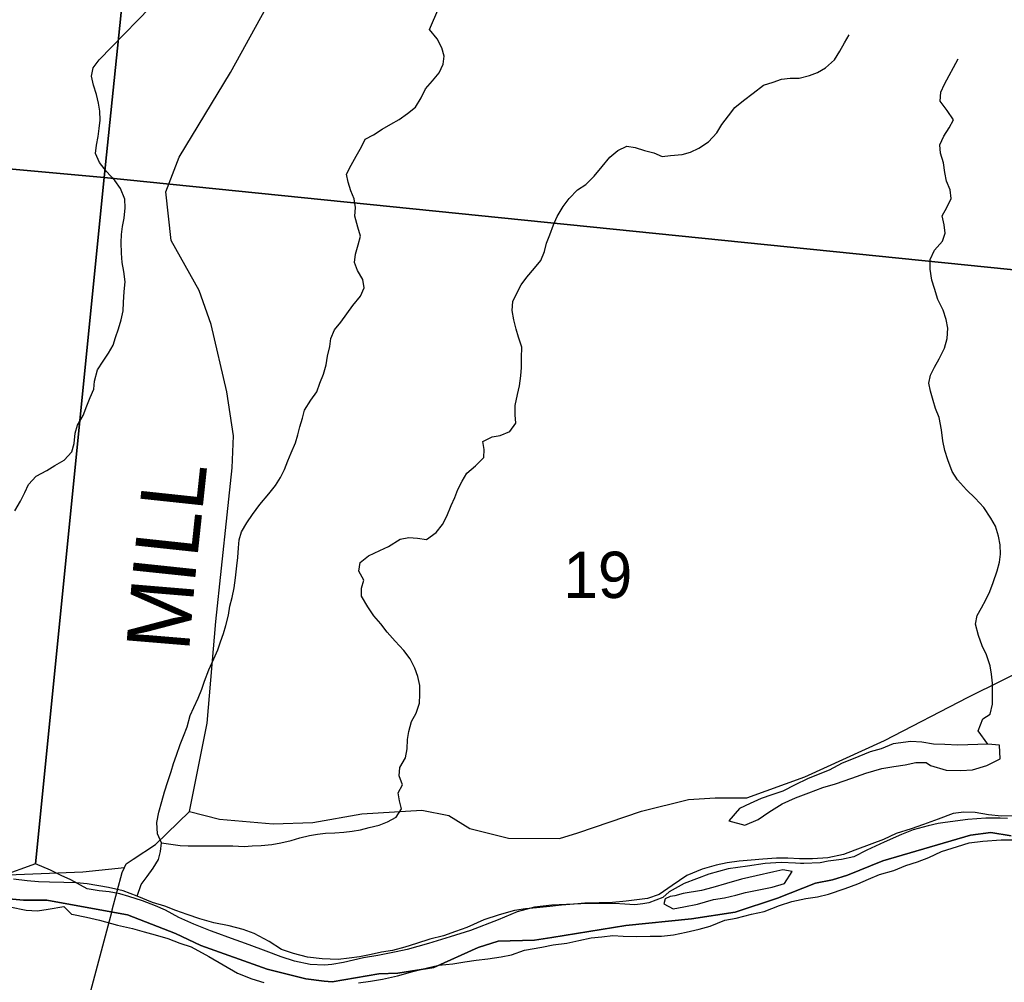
# Model space of a CAD drawing. Extents: x 0 to 34, y -4 to 22.
# Drawn here: x 7.021 to 7.647, y 17.313 to 17.925 of the extents above; entities that cross this region are included whole.
import ezdxf

# ---------------------------------------------------------------- set-up
doc = ezdxf.new("R2010")
doc.units = 0
for name, color, linetype in [('GM_X_County_Road', 7, 'Continuous'), ('GM_X_County_Road_Text', 7, 'Continuous'), ('GM_X_Major_River', 7, 'Continuous'), ('GM_X_Minor_Lake', 7, 'Continuous'), ('GM_X_Minor_River', 7, 'Continuous'), ('GM_X_Section', 7, 'Continuous'), ('GM_X_Section_Text', 7, 'Continuous'), ('GM_X_Township', 7, 'Continuous')]:
    doc.layers.add(name, color=color, linetype=linetype)

msp = doc.modelspace()

# ---------------------------------------------------------------- linework, layer by layer
at = {"layer": 'GM_X_County_Road'}
for points in [[(7.09297, 17.39172), (7.10722, 17.40105), (7.12874, 17.42204), (7.13996, 17.47822), (7.14547, 17.54279), (7.15263, 17.61054), (7.15587, 17.64042), (7.1568, 17.66071), (7.15252, 17.68885), (7.14264, 17.73152), (7.13503, 17.75305), (7.11718, 17.78491), (7.11377, 17.81597), (7.1222, 17.838), (7.15476, 17.89165), (7.19681, 17.96794), (7.24156, 18.04266), (7.28905, 18.14179), (7.32426, 18.22106), (7.33601, 18.25915), (7.33871, 18.2913)], [(7.12874, 17.42204), (7.14789, 17.41714), (7.18205, 17.41411), (7.2072, 17.41498), (7.23831, 17.42056), (7.27658, 17.4228), (7.29363, 17.41955), (7.3071, 17.41129), (7.33158, 17.40496), (7.36392, 17.4049), (7.37576, 17.40842), (7.41611, 17.42211), (7.44593, 17.42959), (7.46306, 17.43061), (7.48311, 17.43078), (7.51998, 17.444), (7.57068, 17.46712), (7.62387, 17.49475), (7.66704, 17.51613), (7.71322, 17.5294), (7.71345, 17.52946)], [(7.07972, 17.35945), (7.08603, 17.38326), (7.08749, 17.38649), (7.08854, 17.38883), (7.09297, 17.39172)], [(6.99189, 17.38097), (7.06091, 17.38372), (7.08749, 17.38649)], [(7.02824, 17.00931), (7.02778, 17.03262), (7.02845, 17.09594), (7.02658, 17.11041), (7.02352, 17.16044), (7.02324, 17.17355), (7.02614, 17.18552), (7.04401, 17.22581), (7.05004, 17.24762), (7.07789, 17.35259), (7.07935, 17.35808), (7.07972, 17.35945)]]:
    msp.add_lwpolyline(points, dxfattribs=at)
at = {"layer": 'GM_X_Major_River'}
for points in [[(7.65438, 17.41915), (7.64501, 17.41912), (7.63673, 17.41986), (7.62821, 17.42141), (7.62099, 17.42159), (7.61427, 17.42069), (7.60482, 17.41719), (7.59536, 17.41368), (7.58752, 17.41094), (7.57808, 17.40797), (7.56995, 17.40416), (7.56265, 17.4014), (7.55184, 17.3974), (7.54455, 17.39464), (7.53459, 17.39248), (7.52494, 17.39192), (7.51664, 17.39186), (7.50916, 17.39232), (7.50193, 17.39223), (7.49335, 17.39164), (7.48584, 17.39103), (7.47833, 17.39042), (7.47054, 17.38927), (7.46354, 17.38784), (7.45464, 17.38539), (7.44491, 17.38136), (7.43564, 17.37491), (7.42746, 17.36923), (7.4199, 17.36675), (7.41319, 17.36585), (7.40647, 17.36495), (7.39762, 17.3641), (7.38932, 17.36404), (7.38021, 17.36374), (7.37324, 17.36311), (7.36519, 17.36251), (7.35794, 17.36162), (7.34936, 17.36076), (7.34238, 17.36014)], [(7.39788, 17.34325), (7.40457, 17.34281), (7.41286, 17.3426), (7.42169, 17.34265), (7.42892, 17.34274), (7.43644, 17.34362), (7.44451, 17.34529), (7.45286, 17.34722), (7.45987, 17.34918), (7.46906, 17.35296), (7.47632, 17.35411), (7.48603, 17.35681), (7.4941, 17.35848), (7.50383, 17.36225), (7.51166, 17.36472), (7.52054, 17.36664), (7.52806, 17.36779), (7.53507, 17.36948), (7.54559, 17.37296), (7.5537, 17.37597), (7.56047, 17.379), (7.56751, 17.38204), (7.57667, 17.38448), (7.58425, 17.38776), (7.59153, 17.38999), (7.59883, 17.39275), (7.60696, 17.39655), (7.61695, 17.39978), (7.6245, 17.40199), (7.63309, 17.40312), (7.64489, 17.40389), (7.65372, 17.40394)], [(7.51189, 17.38396), (7.50602, 17.38491), (7.50037, 17.38372), (7.48906, 17.38106), (7.47964, 17.37889), (7.4702, 17.37618), (7.46157, 17.37373), (7.45429, 17.37177), (7.44273, 17.36992), (7.43734, 17.36845), (7.43439, 17.36799), (7.43114, 17.36647), (7.43025, 17.36328), (7.43633, 17.36019), (7.44305, 17.36136), (7.45166, 17.36302), (7.46191, 17.36597)], [(7.46191, 17.36597), (7.46889, 17.36713), (7.47616, 17.36882), (7.48237, 17.37054), (7.4907, 17.3722), (7.49931, 17.37385), (7.50714, 17.37633), (7.51189, 17.38396)], [(7.34238, 17.36014), (7.33539, 17.35897), (7.32569, 17.35628), (7.31597, 17.35304), (7.30514, 17.34824), (7.29785, 17.34575), (7.29028, 17.343), (7.28166, 17.34081), (7.27303, 17.33808), (7.26574, 17.33586), (7.25792, 17.33365), (7.25093, 17.33249), (7.2442, 17.33105), (7.23694, 17.32963), (7.23023, 17.32873), (7.22324, 17.32783), (7.21309, 17.32835), (7.20375, 17.32939), (7.19497, 17.33175), (7.18728, 17.33434), (7.17938, 17.33935), (7.16987, 17.3444), (7.16298, 17.34698), (7.15394, 17.34934), (7.14435, 17.35119), (7.13532, 17.35382), (7.12736, 17.35642), (7.1202, 17.35901), (7.11305, 17.36186), (7.10534, 17.36419), (7.09554, 17.36818), (7.08653, 17.37161), (7.07722, 17.37371), (7.06363, 17.37592), (7.05695, 17.37662), (7.04893, 17.37682), (7.03983, 17.37705), (7.03288, 17.37722), (7.02567, 17.37794), (7.01686, 17.37896)], [(7.01454, 17.36138), (7.02492, 17.35925), (7.03213, 17.3588), (7.03886, 17.35997), (7.0488, 17.36159), (7.0538, 17.35682)], [(7.0538, 17.35682), (7.05403, 17.35665), (7.06335, 17.35481), (7.0716, 17.353), (7.08302, 17.34978), (7.09261, 17.34767), (7.10005, 17.34561), (7.10695, 17.34357), (7.11492, 17.34123), (7.12261, 17.33836), (7.12978, 17.33605), (7.14113, 17.32988), (7.15009, 17.32458), (7.15932, 17.31927), (7.16833, 17.31557), (7.17603, 17.31324)], [(7.23625, 17.31307), (7.24377, 17.31422), (7.25156, 17.31536), (7.26099, 17.31753), (7.27069, 17.32023), (7.28012, 17.32267), (7.28739, 17.32436), (7.29625, 17.32521), (7.30377, 17.32635), (7.31103, 17.32751), (7.31854, 17.32839), (7.32687, 17.32952), (7.3336, 17.33095), (7.34171, 17.33396), (7.35273, 17.33582), (7.35999, 17.33724), (7.36859, 17.33837), (7.37639, 17.34004), (7.38419, 17.34172), (7.3909, 17.34235), (7.39788, 17.34325)]]:
    msp.add_lwpolyline(points, dxfattribs=at)
at = {"layer": 'GM_X_Minor_Lake'}
for points in [[(7.63629, 17.46478), (7.61727, 17.46419), (7.60898, 17.46466), (7.60176, 17.46484), (7.5943, 17.4661), (7.58735, 17.46654), (7.57607, 17.46495), (7.5685, 17.46193), (7.56149, 17.45997), (7.55067, 17.45543), (7.54363, 17.45266), (7.53549, 17.44832), (7.52846, 17.44556), (7.5217, 17.44279), (7.51384, 17.43898), (7.50597, 17.43489), (7.49896, 17.43266), (7.4922, 17.43016), (7.48516, 17.42713), (7.47839, 17.42382), (7.47176, 17.41597), (7.48186, 17.41331), (7.49025, 17.41684), (7.49706, 17.42149), (7.5055, 17.42689), (7.51416, 17.43068), (7.52254, 17.43395), (7.53146, 17.4372), (7.53955, 17.43967), (7.54981, 17.44315), (7.55873, 17.4464), (7.56898, 17.44936), (7.5765, 17.4505), (7.58376, 17.45166), (7.59049, 17.4531), (7.59718, 17.45319)], [(7.59718, 17.45319), (7.59981, 17.45126), (7.6099, 17.44833), (7.61926, 17.4481), (7.6265, 17.44845), (7.63567, 17.45116), (7.64408, 17.4555), (7.64376, 17.46406), (7.63629, 17.46478)]]:
    msp.add_lwpolyline(points, dxfattribs=at)
at = {"layer": 'GM_X_Minor_River'}
for points in [[(7.0178, 17.61319), (7.02138, 17.61928), (7.02415, 17.62485), (7.02637, 17.62989), (7.03127, 17.63516), (7.03802, 17.6388), (7.04316, 17.64192), (7.0491, 17.6453), (7.054, 17.65057), (7.05543, 17.6559), (7.05608, 17.66257), (7.0575, 17.66763), (7.06108, 17.67372), (7.06359, 17.67983), (7.06555, 17.68514), (7.06805, 17.69045), (7.0684, 17.69552), (7.07039, 17.70271), (7.07396, 17.70826), (7.07726, 17.71329), (7.08028, 17.71832), (7.08171, 17.72338), (7.08367, 17.72869), (7.08537, 17.73455), (7.08654, 17.74014), (7.08689, 17.74548), (7.08728, 17.75243), (7.08792, 17.75857), (7.08696, 17.76527), (7.08598, 17.7709), (7.08555, 17.77678), (7.0854, 17.78374), (7.08548, 17.78881), (7.0861, 17.79388), (7.08726, 17.79921), (7.0879, 17.80562), (7.08773, 17.81123), (7.0849, 17.81796), (7.08124, 17.8231), (7.07599, 17.8288), (7.07154, 17.83448), (7.06896, 17.84014), (7.06958, 17.84547), (7.07075, 17.85107), (7.07137, 17.85614), (7.07199, 17.86147), (7.07182, 17.86709), (7.07083, 17.87218), (7.06959, 17.87782), (7.06782, 17.88373), (7.06658, 17.88936), (7.06747, 17.89469), (7.0713, 17.89971), (7.11193, 17.9415)], [(7.09554, 17.36818), (7.09806, 17.3756), (7.10189, 17.38062), (7.10572, 17.3859), (7.10903, 17.39146), (7.11045, 17.39652), (7.11108, 17.40212), (7.1085, 17.40778), (7.10809, 17.415), (7.10927, 17.42167), (7.11125, 17.42832), (7.11296, 17.43444), (7.11495, 17.44109), (7.11719, 17.44747), (7.11861, 17.45253), (7.12058, 17.45784), (7.12283, 17.46449), (7.12506, 17.4698), (7.1273, 17.47591), (7.12929, 17.4831), (7.13152, 17.48814), (7.13429, 17.49398), (7.13653, 17.49983), (7.13822, 17.50488), (7.14101, 17.51205), (7.14434, 17.51895), (7.14685, 17.52479), (7.14854, 17.52984), (7.1505, 17.53516), (7.15192, 17.54021), (7.15364, 17.54687), (7.15453, 17.55247), (7.15597, 17.55806), (7.15714, 17.56419), (7.15805, 17.57059), (7.15898, 17.57806), (7.1596, 17.5834), (7.15997, 17.58954), (7.16032, 17.59462), (7.16175, 17.59967), (7.16532, 17.6055), (7.16889, 17.61079), (7.17354, 17.61713), (7.17927, 17.62399), (7.18338, 17.62927), (7.18667, 17.63429), (7.18916, 17.63933), (7.19139, 17.64491), (7.19335, 17.64996), (7.19613, 17.65633), (7.19756, 17.66139), (7.19898, 17.66644), (7.20068, 17.67203), (7.20183, 17.67709), (7.20595, 17.68344), (7.20979, 17.68873), (7.21175, 17.69431), (7.21399, 17.69989), (7.21569, 17.70601), (7.21659, 17.71134), (7.21803, 17.71747), (7.21865, 17.72254), (7.22088, 17.72812), (7.22498, 17.73313), (7.22881, 17.73842), (7.23265, 17.7437), (7.23756, 17.7495), (7.23979, 17.75481), (7.23907, 17.76017), (7.23569, 17.76584), (7.23364, 17.77095), (7.23426, 17.77629), (7.23597, 17.78214), (7.2374, 17.78773), (7.23589, 17.79337), (7.23386, 17.80035), (7.23423, 17.80596), (7.23351, 17.81132), (7.23146, 17.81643), (7.22968, 17.82207), (7.2287, 17.82717), (7.23147, 17.83274), (7.23477, 17.83857), (7.23808, 17.84439), (7.24057, 17.84943), (7.2457, 17.85202), (7.25138, 17.85568), (7.25678, 17.8588), (7.26218, 17.86192), (7.26733, 17.86558), (7.27248, 17.86978), (7.27605, 17.8756), (7.27883, 17.88144), (7.28319, 17.88645), (7.28756, 17.89146), (7.29006, 17.89703), (7.29068, 17.9021), (7.28916, 17.90747), (7.28632, 17.91313), (7.28133, 17.91909), (7.29263, 17.94527)], [(7.36252, 17.80017), (7.36638, 17.80653), (7.3702, 17.81155), (7.37538, 17.81708), (7.38079, 17.82047), (7.38596, 17.82573), (7.39115, 17.83206), (7.39606, 17.83787), (7.40121, 17.84206), (7.40688, 17.84491), (7.41221, 17.84403), (7.41806, 17.84206), (7.42392, 17.84063), (7.42924, 17.83841), (7.43459, 17.83886), (7.44209, 17.83954), (7.4472, 17.84106), (7.4526, 17.84365), (7.45881, 17.84756), (7.46399, 17.85336), (7.46729, 17.85865), (7.4714, 17.8642), (7.4755, 17.86948), (7.48092, 17.87394), (7.48715, 17.87865), (7.49366, 17.88363), (7.49985, 17.88567), (7.50522, 17.88745), (7.51059, 17.88817), (7.51647, 17.88808), (7.52292, 17.88984), (7.52803, 17.89163), (7.53317, 17.89476), (7.53887, 17.89975), (7.54217, 17.90531), (7.5452, 17.91061), (7.54823, 17.91564)], [(7.63629, 17.46478), (7.63013, 17.47325), (7.63324, 17.48091), (7.6378, 17.48382), (7.63924, 17.49021), (7.63934, 17.49609), (7.6392, 17.50358), (7.63876, 17.5092), (7.63778, 17.51456), (7.63549, 17.52155), (7.63264, 17.52721), (7.63035, 17.53393), (7.6286, 17.54117), (7.62949, 17.54651), (7.63225, 17.55154), (7.63501, 17.55658), (7.63751, 17.56188), (7.63974, 17.56746), (7.64227, 17.5749), (7.6437, 17.5805), (7.64432, 17.58557), (7.64416, 17.59145), (7.64318, 17.59708), (7.64114, 17.60326), (7.63829, 17.60838), (7.63385, 17.61514), (7.62834, 17.62111), (7.62281, 17.62654), (7.61703, 17.63278), (7.61365, 17.63818), (7.61083, 17.64545), (7.60905, 17.65136), (7.60782, 17.65752), (7.60687, 17.66449), (7.6054, 17.67253), (7.60308, 17.67818), (7.60156, 17.68329), (7.59979, 17.6892), (7.59881, 17.69429), (7.59996, 17.69935), (7.60245, 17.70439), (7.60549, 17.70969), (7.60881, 17.71659), (7.61052, 17.72271), (7.61089, 17.72912), (7.60992, 17.73475), (7.60788, 17.74066), (7.60452, 17.7474), (7.60249, 17.75438), (7.60071, 17.75975), (7.59976, 17.76672), (7.59959, 17.77287), (7.60237, 17.77871), (7.60755, 17.78451), (7.60924, 17.78956), (7.60852, 17.79492), (7.60728, 17.80055), (7.61031, 17.80585), (7.61309, 17.81168), (7.61237, 17.81704), (7.61006, 17.82269), (7.60908, 17.82806), (7.60811, 17.83422), (7.60635, 17.8404), (7.6059, 17.84575), (7.6084, 17.85132), (7.6117, 17.85662), (7.61446, 17.86165), (7.61055, 17.8676), (7.6061, 17.87355), (7.60646, 17.87916), (7.60869, 17.8842), (7.61172, 17.88976), (7.61448, 17.8948), (7.61752, 17.90036)], [(7.11108, 17.40212), (7.12282, 17.40033), (7.1279, 17.40025), (7.13325, 17.40017), (7.13886, 17.40008), (7.14395, 17.40026), (7.15037, 17.40016), (7.15625, 17.40007), (7.16347, 17.39969), (7.16856, 17.40014), (7.17445, 17.40031), (7.18114, 17.40101), (7.18678, 17.40199), (7.19349, 17.40348), (7.19887, 17.40527), (7.20505, 17.40678), (7.21014, 17.4075), (7.21523, 17.40822), (7.22112, 17.40839), (7.22701, 17.40883), (7.23211, 17.40955), (7.23747, 17.41027), (7.24311, 17.41178), (7.24929, 17.41329), (7.25468, 17.41534), (7.26008, 17.41846), (7.26364, 17.42375), (7.26239, 17.42885), (7.26141, 17.43395), (7.26417, 17.43898), (7.26212, 17.44463), (7.26248, 17.44997), (7.26606, 17.45606), (7.26723, 17.46192), (7.26733, 17.4678), (7.26821, 17.47287), (7.26993, 17.47926), (7.27296, 17.48456), (7.27494, 17.49094), (7.27529, 17.49628), (7.27513, 17.50216), (7.27388, 17.5078), (7.2721, 17.51317), (7.26899, 17.5191), (7.26507, 17.52425), (7.25955, 17.53021), (7.25456, 17.53591), (7.25037, 17.54132), (7.24591, 17.54647), (7.24226, 17.55214), (7.2381, 17.55889), (7.23818, 17.56397), (7.23961, 17.56903), (7.23649, 17.57469), (7.23739, 17.58029), (7.24254, 17.58448), (7.24982, 17.58784), (7.25521, 17.59043), (7.26278, 17.59512), (7.26815, 17.59611), (7.27376, 17.59575), (7.27936, 17.59486), (7.28559, 17.5993), (7.28968, 17.60432), (7.29245, 17.60962), (7.29524, 17.61653), (7.29746, 17.62157), (7.29942, 17.62662), (7.30219, 17.63192), (7.30521, 17.63695), (7.31064, 17.64168), (7.31581, 17.64694), (7.31616, 17.65201), (7.31518, 17.65711), (7.32112, 17.66022), (7.32621, 17.66094), (7.33241, 17.66352), (7.33624, 17.6688), (7.3358, 17.67416), (7.33589, 17.68004), (7.33735, 17.68696), (7.33851, 17.69256), (7.33942, 17.69896), (7.33978, 17.7043), (7.33988, 17.71045), (7.34, 17.71713), (7.33796, 17.72358), (7.33645, 17.72868), (7.33494, 17.73459), (7.33397, 17.74048), (7.33433, 17.74609), (7.33683, 17.7514), (7.33959, 17.7567), (7.34315, 17.76172), (7.34806, 17.76726), (7.35216, 17.77227), (7.35439, 17.77785), (7.35582, 17.78317), (7.35778, 17.78849), (7.36029, 17.79486), (7.36252, 17.80017)]]:
    msp.add_lwpolyline(points, dxfattribs=at)
at = {"layer": 'GM_X_Section'}
for points in [[(6.41744, 18.64125), (7.15014, 18.55903), (7.07455, 17.825), (6.34502, 17.8912)], [(7.15014, 18.55903), (7.82864, 18.48717), (7.74884, 17.75662), (7.07455, 17.825)]]:
    msp.add_lwpolyline(points, close=True, dxfattribs=at)
for points in [[(6.34502, 17.8912), (7.07455, 17.825), (7.0309, 17.38883), (7.00862, 17.38072)], [(7.6489, 17.4175), (7.64411, 17.41786), (7.63504, 17.41776), (7.62356, 17.41691), (7.60913, 17.41505), (7.60485, 17.41433), (7.59843, 17.41285), (7.58878, 17.41037), (7.58153, 17.4073), (7.5705, 17.40244), (7.55947, 17.39732), (7.55113, 17.39321), (7.54337, 17.39149), (7.53482, 17.39032), (7.52973, 17.38934), (7.51933, 17.389), (7.5172, 17.38904), (7.514, 17.38911), (7.50494, 17.38954), (7.4948, 17.38893), (7.48357, 17.38728), (7.47128, 17.38564), (7.45895, 17.38214), (7.44337, 17.3763), (7.43367, 17.37089), (7.42961, 17.36723), (7.42075, 17.36392), (7.417, 17.3632), (7.41193, 17.36276), (7.40553, 17.36315), (7.39888, 17.36354), (7.37755, 17.3634), (7.35913, 17.36242), (7.34818, 17.36129), (7.3372, 17.3583), (7.3251, 17.35319), (7.30737, 17.34633), (7.2945, 17.3423), (7.28083, 17.33802), (7.26716, 17.33428), (7.2602, 17.33281), (7.24842, 17.33036), (7.23933, 17.32893), (7.22675, 17.32597), (7.21926, 17.32478), (7.21472, 17.32433), (7.2054, 17.32477), (7.19557, 17.32683), (7.18709, 17.32965), (7.17756, 17.33329), (7.1667, 17.33723), (7.1532, 17.34202), (7.14737, 17.34426), (7.14208, 17.34622), (7.1315, 17.35042), (7.12198, 17.3546), (7.11353, 17.35929), (7.10718, 17.36207), (7.09898, 17.36516), (7.09023, 17.36799), (7.0844, 17.3697), (7.07775, 17.37089), (7.07137, 17.37154), (7.06366, 17.37276), (7.05337, 17.37855), (7.04729, 17.38133), (7.04042, 17.38465), (7.0309, 17.38883), (7.07455, 17.825), (7.74884, 17.75662)]]:
    msp.add_lwpolyline(points, dxfattribs=at)
at = {"layer": 'GM_X_Township'}
for points in [[(7.65116, 17.40663), (7.63827, 17.4087), (7.62533, 17.40704), (7.5696, 17.39064), (7.54706, 17.38157), (7.53749, 17.37847), (7.5267, 17.37648), (7.50263, 17.36692), (7.47562, 17.35793), (7.44792, 17.35369), (7.40615, 17.34951), (7.35923, 17.34184), (7.34807, 17.34029), (7.32494, 17.33955), (7.31227, 17.33554), (7.28415, 17.32283), (7.26133, 17.31922), (7.2491, 17.31887), (7.21954, 17.31378), (7.21433, 17.31409), (7.20278, 17.31553), (7.17807, 17.32169), (7.13589, 17.33678), (7.1198, 17.34439), (7.08941, 17.35624), (7.0695, 17.35989), (7.03819, 17.36556), (7.02329, 17.36554), (6.99285, 17.36842)], [(6.99285, 17.36842), (7.02329, 17.36554), (7.03819, 17.36556), (7.0695, 17.35989), (7.08941, 17.35624), (7.1198, 17.34439), (7.13589, 17.33678), (7.17807, 17.32169), (7.20278, 17.31553), (7.21433, 17.31409), (7.21954, 17.31378), (7.2491, 17.31887), (7.26133, 17.31922), (7.28415, 17.32283), (7.31227, 17.33554), (7.32494, 17.33955), (7.34807, 17.34029), (7.35923, 17.34184), (7.40615, 17.34951), (7.44792, 17.35369), (7.47562, 17.35793), (7.50263, 17.36692), (7.5267, 17.37648), (7.53749, 17.37847), (7.54706, 17.38157), (7.5696, 17.39064), (7.62533, 17.40704), (7.63827, 17.4087), (7.65116, 17.40663)]]:
    msp.add_lwpolyline(points, dxfattribs=at)

# ---------------------------------------------------------------- texts
at = {"layer": 'GM_X_County_Road_Text'}
for s, rotation, p in [('L', 83.89394, (7.1369, 17.6122)), ('L', 83.89407, (7.13372, 17.58245)), ('I', 83.97873, (7.132, 17.56613)), ('M', 85.24812, (7.12843, 17.5231))]:
    msp.add_text(s, height=0.04, rotation=rotation, dxfattribs=at).set_placement(p)
at = {"layer": 'GM_X_Section_Text'}
msp.add_text('19', height=0.029444, rotation=0.00001, dxfattribs=at).set_placement((7.36651, 17.55771))

doc.saveas('drawing.dxf')
